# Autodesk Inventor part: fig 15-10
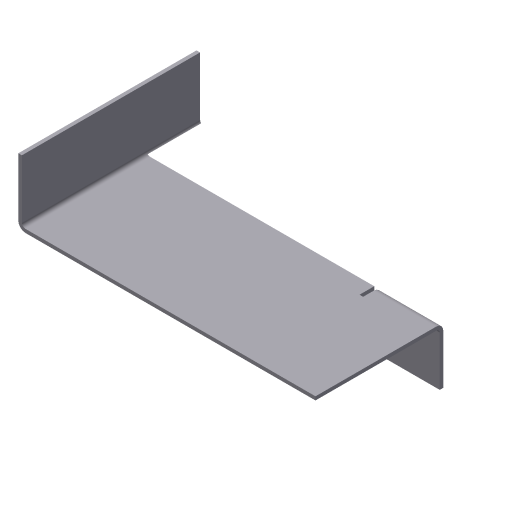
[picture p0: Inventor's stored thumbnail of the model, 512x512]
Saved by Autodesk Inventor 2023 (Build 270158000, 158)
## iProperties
Created: 2002-04
Part Number: fig 15-10
Material: Aluminum-6061
Document SubType Name: Sheet Metal
Density: 1 g/cm^3
Sheet Metal Rule: Default
Appearance: Aluminum - Flat-1
Control State: 0
Master: False
Checked Out: False
Shininess: 77.0
Angle Display Precision: 2
Document Length Units: 11269
Document Angle Units: 11279
Document Time Units: 11290
Document Mass Units: 11283
Document Length Units Precision: 3
Document Angle Units Precision: 2
Density: 0.0
Volumn: 0.0
Area: 0.0
PropertySet Name: Model Information
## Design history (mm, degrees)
node "Face1"
  sketch "Sketch1"
    geometry: L1 (-49.559, 19.574)-(-49.559, -30.426); L2 (-49.559, -30.426)-(50.441, -30.426); L3 (50.441, -30.426)-(50.441, 19.574); L4 (50.441, 19.574)-(32.941, 19.574); L5 (32.941, 19.574)-(32.941, 4.574); L6 (32.941, 4.574)-(-32.059, 4.574); L7 (-32.059, 4.574)-(-32.059, 19.574); L8 (-32.059, 19.574)-(-49.559, 19.574)
    constraints: 16 end point, 6 parallel, 2 equal length, 1 perpendicular, 1 vertical
    dimensions: "d0" = 100 distance of L1.end L2.end; "d1" = 65 distance of L5.end L6.end; "d2" = 15 distance of L6.end L7.end; "d3" = 50 distance of L1.start L1.end
sketch "Sketch2"
  geometry: L1 (100, 0)-(0, 0) reference; L2 (17.5, 50)-(17.5, 35) reference; L3 (82.5, 50)-(82.5, 0)
  constraints: 2 end point, 1 parallel, 1 point on line
sketch "Sketch3"
  geometry: L1 (81.369, -50)-(0, -50) reference; L2 (17.5, 0)-(17.5, -50)
  constraints: 2 end point, 1 perpendicular, 1 point on line
feature "Fold2" sketch "Sketch3" dims "d8" = 1 (= BendRadius), "d9" = 90 deg, "d10" = 1 (= BendRadius), "d14" = 1 (= BendReliefWidth), "d15" = 0.5 (= BendReliefDepth), "d16" = 2 (= MinimumRemnant), "d20" = 1 (= Thickness), "SeamGap" = 0.01
sketch "Sketch4"
  geometry: L1 (17.5, 0)-(17.5, -50) reference; L2 (-63.869, -15)-(0, -15) reference; L3 (0, -15)-(17.5, -15)
  constraints: 2 end point, 1 collinear, 1 point on line
feature "Fold3" sketch "Sketch4" dims "d11" = 1 (= BendRadius), "d12" = 90 deg, "d13" = 1 (= BendRadius), "d17" = 1, "d18" = 3, "d19" = 2 (= MinimumRemnant), "d20" = 1 (= Thickness), "SeamGap" = 0.01
body "Solid1"
face "Plate1" dims "d20" = 1 (= Thickness)
other parameters: "Thickness" = 1, "BendRadius" = 1 (= Thickness), "BendReliefWidth" = 1 (= Thickness), "BendReliefDepth" = 0.5 (= 0.5 x Thickness), "CornerReliefSize" = 4 (= 4 x Thickness), "MinimumRemnant" = 2 (= 2 x Thickness), "TransitionRadius" = 1 (= BendRadius), "d4" = 1 (= BendRadius), "JacobiRadiusSize" = 1 (= Thickness), "GapSize" = 1 (= Thickness)
